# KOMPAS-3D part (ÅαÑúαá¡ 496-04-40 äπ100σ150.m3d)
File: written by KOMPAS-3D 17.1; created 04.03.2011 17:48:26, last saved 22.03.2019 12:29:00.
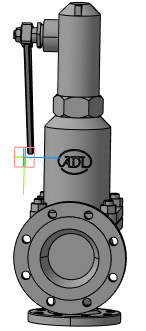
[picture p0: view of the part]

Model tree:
1. Плоскость XY
2. Плоскость ZX
3. Плоскость ZY
4. Ось X
5. Ось Y
6. Ось Z
7. Начало координат
8. Операция без истории:2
